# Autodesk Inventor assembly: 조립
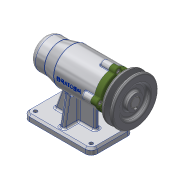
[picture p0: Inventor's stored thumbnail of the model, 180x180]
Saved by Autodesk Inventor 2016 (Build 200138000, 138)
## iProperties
Created: 2019-07
Part Number: 조립
Material: 일반
Document SubType Name: Assembly
Designer: 605-08
Author: 605-08
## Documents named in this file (11)
- C:\Users\605-08\Desktop\490704V1064\조립.iam
- C:\Users\605-08\Desktop\490704V1064\1.본체.ipt
- C:\Users\605-08\Desktop\490704V1064\베어링 6004.ipt
- C:\Users\605-08\Desktop\490704V1064\베어링 51202.ipt
- C:\Users\605-08\Desktop\490704V1064\어댑터슬리브.ipt
- C:\Users\605-08\Desktop\490704V1064\축.ipt
- C:\Users\605-08\Desktop\490704V1064\볼트 M4.ipt
- C:\Users\605-08\Desktop\490704V1064\커버.ipt
- C:\Users\605-08\Desktop\490704V1064\V벨트풀리.ipt
- C:\Users\605-08\Desktop\490704V1064\키 5 x 5 x 16.ipt
- C:\Users\605-08\Desktop\490704V1064\멈춤나사 M3.ipt
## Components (2 placed, 2 different names)
1. 1.본체:1
2. V벨트풀리:1
